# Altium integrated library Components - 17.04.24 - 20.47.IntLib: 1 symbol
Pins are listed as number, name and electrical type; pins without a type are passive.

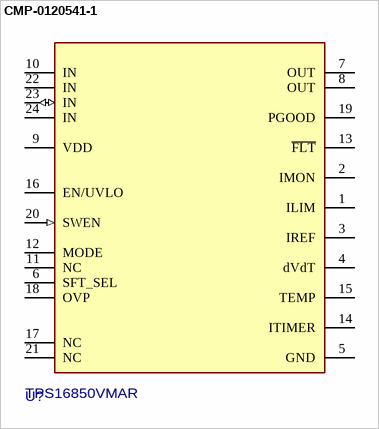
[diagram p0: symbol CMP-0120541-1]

## CMP-0120541-1
designator U?, comment TPS16850VMAR
9 - 80 V , 4.3 mΩ, 20 A Stackable eFuse with Accurate & Fast Current Monitor; Manufacturer: Texas Instruments; SizeZ_mm: 1.5mm; AEC Qualified: No; Max Supply Voltage: 80V; Min Supply Voltage: 9V; Number Of Outputs: 1; Standoff Height: 0mm; TJmax_C: +125°C
footprint VMA0023A-MFG
pins: 1 ILIM, 2 IMON, 3 IREF, 4 dVdT, 5 GND (power), 6 SFT_SEL, 7 OUT, 8 OUT, 9 VDD, 10 IN, 11 NC, 12 MODE (power), 13 ~{FLT} (power), 14 ITIMER, 15 TEMP, 16 EN/UVLO (oc), 17 NC, 18 OVP, 19 PGOOD, 20 SWEN (in), 21 NC (oc), 22 IN, 23 IN (io), 24 IN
